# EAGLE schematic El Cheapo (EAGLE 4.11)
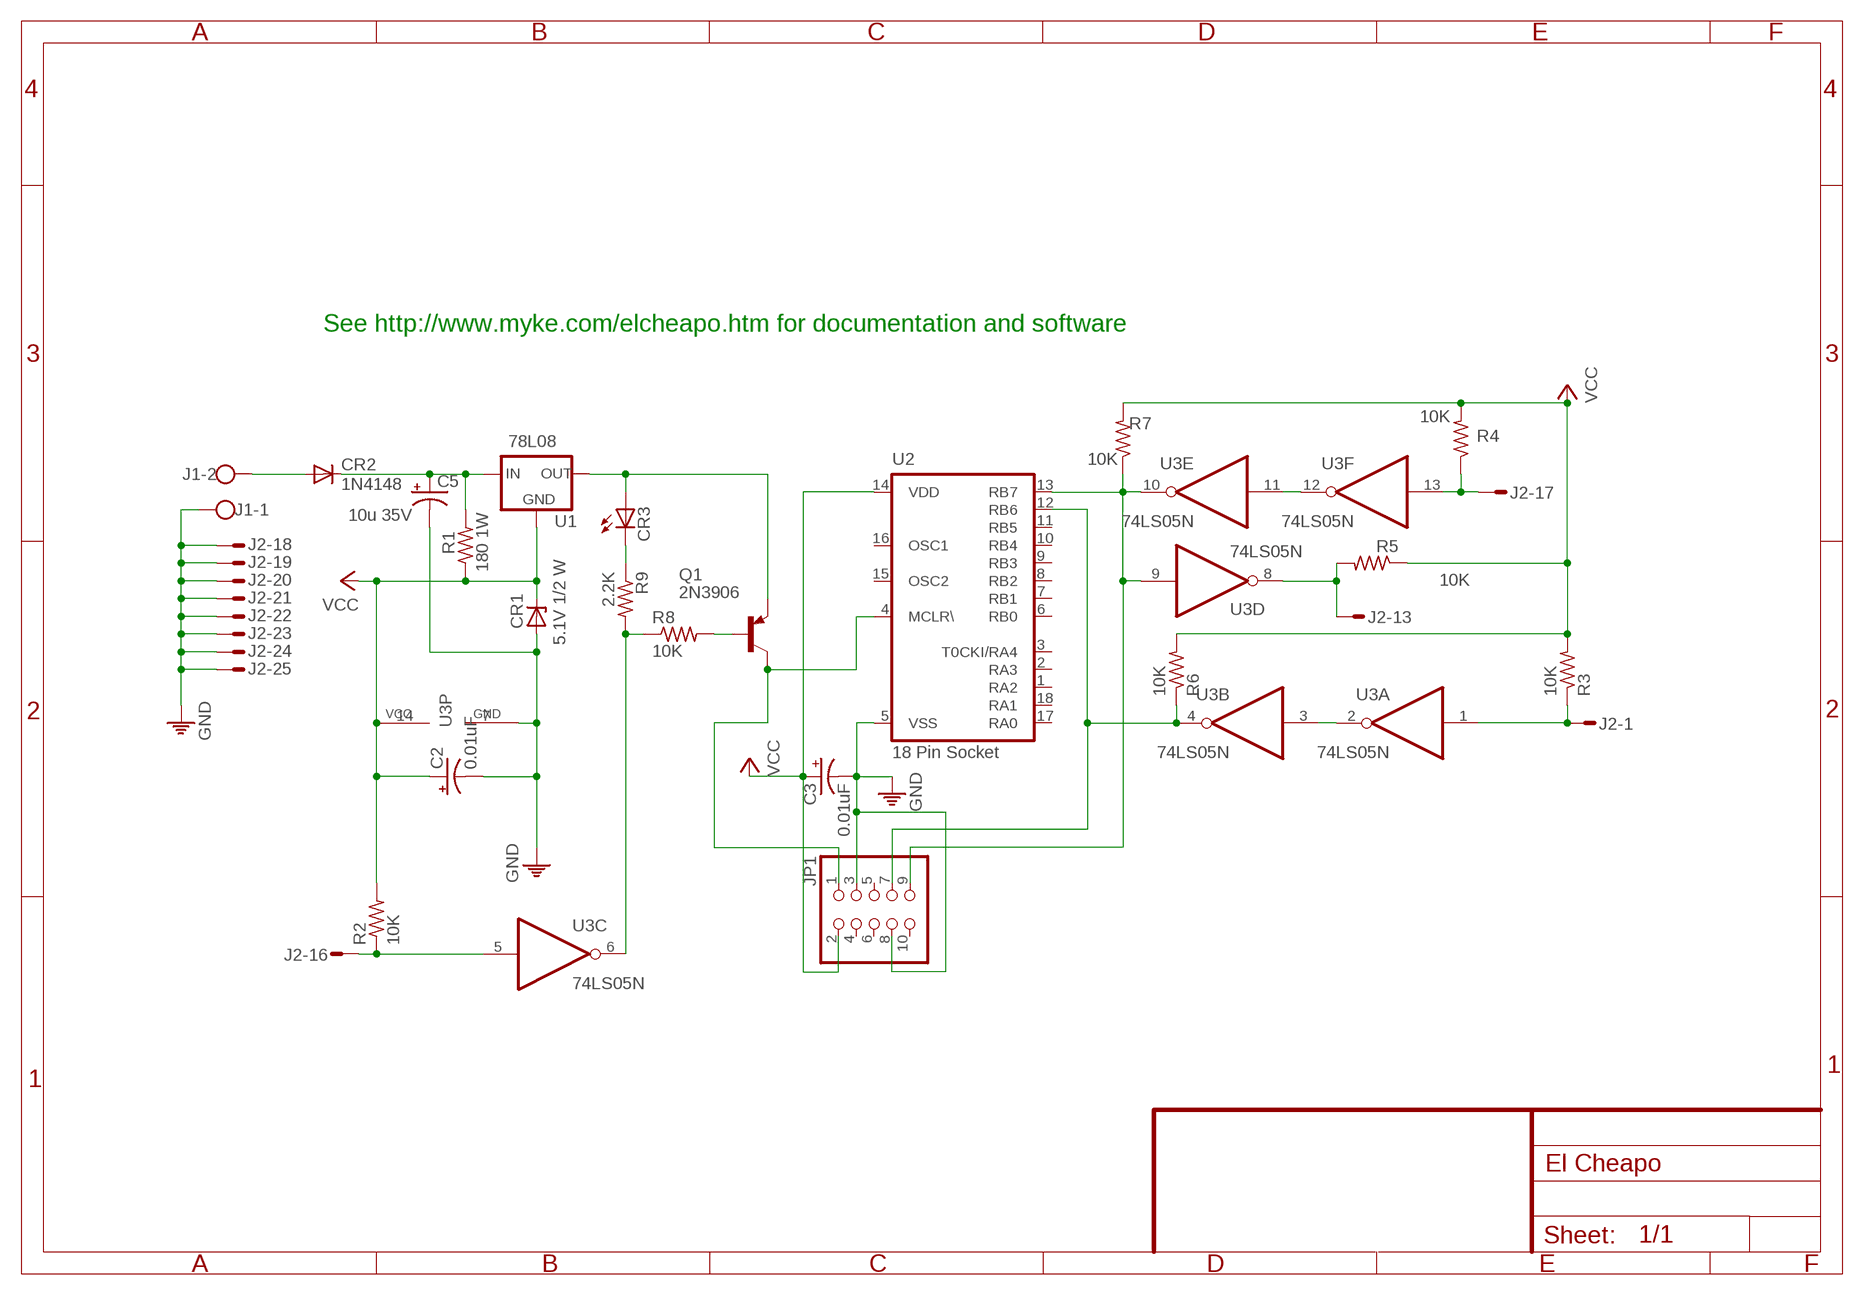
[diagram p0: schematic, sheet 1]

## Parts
C2  0.01uF  CPOL-USE2.5-5  [E2,5-5]
C3  0.01uF  CPOL-USE2.5-5  [E2,5-5]
C5  10u 35V  CPOL-USB45181A  [B45181A]
CR1  5.1V 1/2 W  ZPD  [DO35Z10]
CR2  1N4148  [DO35-10]
CR3  LED5MM  [LED5MM]
J1  W237-102  [W237-102]
J2  M25VS  [M25V]
JP1  PINHD-2X5  [2X05]
Q1  2N3906  [TO92]
R1  180 1W  R-US_0411/12  [0411/12]
R2  10K  R-US_0207/12  [0207/12]
R3  10K  R-US_0207/12  [0207/12]
R4  10K  R-US_0207/12  [0207/12]
R5  10K  R-US_0207/12  [0207/12]
R6  10K  R-US_0207/12  [0207/12]
R7  10K  R-US_0207/12  [0207/12]
R8  10K  R-US_0207/12  [0207/12]
R9  2.2K  R-US_0207/12  [0207/12]
U1  78L08  78LXX  [78LXX]
U2  18 Pin Socket  PIC16F84AP  [DIL18]
U3  74LS05N  [DIL14]

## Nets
GND: C2.- C3.- C5.- CR1.A J1.1 J2.18 J2.19 J2.20 J2.21 J2.22 J2.23 J2.24 J2.25 JP1.3 JP1.8 U2.5(VSS) U3.7(P:GND)
MCLR: JP1.1 Q1.1(C) U2.4(MCLR\)
N$1: U3.2(A:O) U3.3(B:I)
N$2: C5.+ CR2.C R1.2 U1.IN
N$3: CR3.A Q1.3(E) U1.OUT
N$4: J2.1 R3.1 U3.1(A:I)
N$6: CR2.A J1.2
N$7: CR3.K(C) R9.1
N$8: R8.1 R9.2 U3.6(C:O)
N$9: Q1.2(B) R8.2
N$10: J2.16 R2.1 U3.5(C:I)
N$12: J2.17 R4.1 U3.13(F:I)
N$13: U3.11(E:I) U3.12(F:O)
N$14: J2.13 R5.2 U3.8(D:O)
RB6-CLK: JP1.7 R6.1 U2.12(RB6) U3.4(B:O)
RB7-DATA: JP1.9 R7.1 U2.13(RB7) U3.9(D:I) U3.10(E:O)
VCC: C2.+ CR1.C R1.1 R2.2 R3.2 R4.2 R5.1 R6.2 R7.2 U1.GND U3.14(P:VCC)
VCC-VDD: C3.+ JP1.2 U2.14(VDD) ; supply symbol labelled VCC
Unconnected: J2.2 J2.3 J2.4 J2.5 J2.6 J2.7 J2.8 J2.9 J2.10 J2.11 J2.12 J2.14 J2.15 JP1.4 JP1.5 JP1.6 JP1.10 U2.1(RA2) U2.2(RA3) U2.3(T0CKI/RA4) U2.6(RB0) U2.7(RB1) U2.8(RB2) U2.9(RB3) U2.10(RB4) U2.11(RB5) U2.15(OSC2) U2.16(OSC1) U2.17(RA0) U2.18(RA1)

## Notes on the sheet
- See http://www.myke.com/elcheapo.htm for documentation and software

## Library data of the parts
C2 C3 C5 = rcl:CPOL-US: POLARIZED CAPACITOR, American symbol
CR1 = diode:ZPD: Z DIODE
CR2 = diode:1N4148: DIODE
CR3 = led:LED: LED
J1 = con-wago-500:W237-102: WAGO SCREW CLAMP
J2 = con-subd:M25?S: SUB-D
JP1 = pinhead:PINHD-2X5: PIN HEADER
Q1 = transistor-pnp:2N3906: PNP Transistor
R1-R9 = rcl:R-US_: RESISTOR, American symbol
U1 = v-reg:78LXX: VOLTAGE REGULATOR
U2 = microchip:PIC16F8*: MICROCONTROLLER 8-Bit PIC16F8X Family - CMOS Flash/EEPROM Pin Compatible : PIC16F83, PIC16CR83, PIC16F84A, PIC16CR84 see also PIC16C*
U3 = 74xx-us:74*05: Hex INVERTER, open collector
